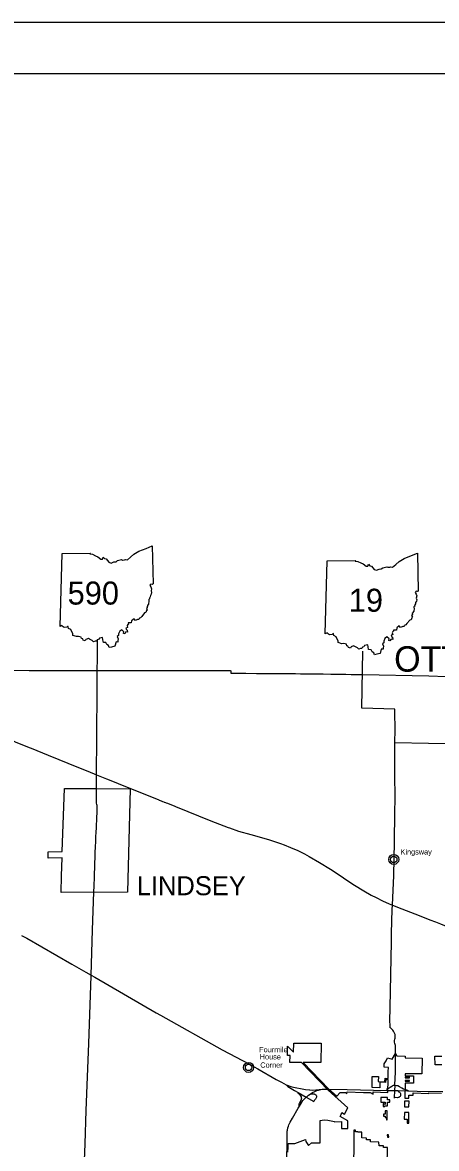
# Model space of a CAD drawing. Extents: x 0 to 798, y 0 to 440.
# Drawn here: x 286.7 to 368.1, y 218.5 to 440 of the extents above; entities that cross this region are included whole.
import ezdxf

# ---------------------------------------------------------------- set-up
doc = ezdxf.new("R2010")
doc.units = 0
for name, color, linetype in [('DV_X_Corp_Line', 7, 'Continuous'), ('GM_X_Adjacent_County_Text', 7, 'Continuous'), ('GM_X_Corporation_Text', 7, 'Continuous'), ('GM_X_County', 7, 'Continuous'), ('GM_X_Interchange_Ramps', 7, 'Continuous'), ('GM_X_Interstate_Route', 7, 'Continuous'), ('GM_X_State_Route', 7, 'Continuous'), ('GM_X_US_Route', 7, 'Continuous'), ('PV_P_Text', 7, 'Continuous'), ('SH_Border', 7, 'Continuous'), ('SH_Cut_Line', 7, 'Continuous')]:
    doc.layers.add(name, color=color, linetype=linetype)

msp = doc.modelspace()

# ---------------------------------------------------------------- linework, layer by layer
at = {"layer": 'DV_X_Corp_Line'}
for points in [[(294.48, 275.7), (291.76, 275.59), (291.77, 276.85), (294.52, 276.95), (294.94, 289.31), (301.23, 289.3), (307.86, 289.23), (307.38, 268.9), (294.27, 268.88), (294.36, 272.12)], [(361.98, 232.58), (361.98, 232.42), (362.83, 232.42), (362.83, 232.58)], [(361.97, 231.73), (362.82, 231.73), (362.82, 231.86), (361.98, 231.86)], [(357.18, 228.51), (357.18, 227.98), (357.22, 227.98), (357.22, 227.62), (358.06, 227.62), (358.06, 227.14), (357.68, 227.35), (357.68, 226.74), (357.97, 226.74), (357.97, 226.89), (358.5, 226.88), (358.5, 227.62), (359, 227.62), (359, 228.1), (358.53, 228.1), (358.54, 228.51)], [(361.86, 226.73), (362.72, 226.71), (362.74, 227.79), (361.87, 227.79)], [(358.02, 225.92), (358.02, 225.27), (357.73, 225.27), (357.73, 224.84), (358.02, 224.84), (358.02, 224.61), (358.34, 224.61), (358.34, 224.15), (358.47, 224.15), (358.46, 224.73), (358.45, 225.52), (358.46, 225.92)], [(361.82, 224.29), (362.35, 224.29), (362.35, 223.5), (362.72, 223.49), (362.72, 225.61), (361.85, 225.61)], [(358.47, 221.16), (358.49, 220.72), (358.74, 220.71), (358.72, 221.16)]]:
    msp.add_lwpolyline(points, close=True, dxfattribs=at)
for points in [[(338.88, 217.79), (338.97, 218.79), (338.97, 219.46), (340.29, 219.48), (340.81, 219.67), (342.38, 220.25), (342.42, 219.91), (342.99, 219.12), (343.56, 219.59), (345.24, 219.62), (345.24, 224), (346.07, 224.15), (346.77, 224.07), (348.07, 223.84), (348.04, 223.78), (349.45, 223.83), (349.45, 222.43), (350.72, 222.45), (350.72, 223.95), (349.21, 224.82), (349.38, 225.18), (349.51, 225.56), (350.06, 225.25), (350.7, 226.51), (346.86, 229.97), (341.6, 235.42), (339.32, 235.42), (339.34, 236.79), (338.84, 236.79), (338.85, 238.66), (340.03, 237.45), (340.06, 239.21), (345.45, 239.21), (345.38, 235.44), (341.9, 235.44), (346.99, 230.17), (348.54, 228.79), (349.19, 229.52), (350.23, 229.5), (350.54, 229.25), (350.56, 229.64), (353.8, 229.54), (355.08, 229.49), (355.71, 229.2), (355.72, 229.63), (358.56, 229.55), (358.62, 232.05), (358.15, 232.06), (358.14, 231.51), (357.02, 231.55), (356.99, 230.44), (355.46, 230.48), (355.52, 232.67), (356.71, 232.65), (356.69, 231.68), (358.01, 231.63), (358.03, 232.32), (358.63, 232.3), (358.66, 233.66), (358.71, 234.45), (357.87, 234.48), (357.88, 235.14), (358.23, 235.77), (358.53, 236.32), (359.42, 236.08), (360.07, 237.16), (360.33, 236.73), (361.98, 236.68), (362, 236.34), (365.32, 236.28), (365.26, 233.17), (361.99, 233.18), (361.98, 232.79), (363.64, 232.79), (363.63, 231.33), (361.97, 231.34), (361.91, 228.41), (362.69, 228.41), (362.69, 229), (363.55, 229.01), (363.59, 229.43), (366.61, 229.34), (366.63, 229.48), (369.16, 229.41)], [(369.23, 234.96), (367.86, 234.98), (367.85, 236.67), (369.22, 236.67)], [(358.45, 215.07), (358.48, 218.73), (357.71, 218.71), (357.71, 219.01), (356.84, 219), (356.83, 219.77), (355.18, 219.8), (355.18, 220.2), (354.36, 220.18), (354.36, 220.56), (353.45, 220.58), (353.47, 221.69), (352.64, 221.72), (352.64, 221.78), (352.21, 221.78), (352.21, 222.11), (351.91, 222.11), (351.89, 219.21), (351.83, 215.37)]]:
    msp.add_lwpolyline(points, dxfattribs=at)
for centre, radius in [((359.74, 275.36), 0.982), ((359.74, 275.36), 0.623), ((331.17, 234.45), 0.982), ((331.17, 234.45), 0.623)]:
    msp.add_circle(centre, radius, dxfattribs=at)
at = {"layer": 'GM_X_County'}
msp.add_lwpolyline([(281.3, 312.63), (287.98, 312.54), (301.39, 312.52), (301.93, 312.52), (302.64, 312.52), (303.69, 312.52), (304.8, 312.52), (305.75, 312.51), (307.02, 312.52), (307.92, 312.52), (308.45, 312.52), (309.05, 312.53), (310.14, 312.54), (310.71, 312.54), (311.7, 312.54), (312.27, 312.55), (314.12, 312.55), (314.59, 312.55), (314.66, 312.55), (314.98, 312.55), (315.76, 312.55), (316.87, 312.55), (317.32, 312.55), (318.39, 312.54), (320.24, 312.53), (320.85, 312.52), (321.76, 312.52), (322.24, 312.51), (322.74, 312.51), (323.44, 312.51), (324.34, 312.52), (327.09, 312.51), (327.58, 312.5), (327.69, 312.49), (327.71, 311.99), (330.61, 311.98), (332.73, 311.96), (333.63, 311.96), (340.32, 311.91), (340.36, 311.91), (340.43, 311.91), (341.36, 311.88), (342.43, 311.87), (344.19, 311.87), (345.88, 311.86), (347.36, 311.83), (348.69, 311.81), (349.44, 311.8), (350.31, 311.79), (351.37, 311.77), (352.15, 311.75), (353.17, 311.73), (353.57, 311.72), (366.64, 311.45), (370.09, 311.37)], dxfattribs=at)
at = {"layer": 'GM_X_Interchange_Ramps'}
for points in [[(360, 230.89), (359.91, 230.89), (359.77, 230.9), (359.65, 230.88), (359.51, 230.81), (359.36, 230.7), (359.01, 230.47), (358.85, 230.39), (358.7, 230.32), (358.54, 230.27), (358.42, 230.23), (358.37, 230.22), (358.37, 229.92)], [(340.9, 229.51), (340.85, 229.43), (341.1, 229.23), (341.28, 229.05), (341.41, 228.86), (341.51, 228.66), (341.55, 228.5), (341.57, 228.33), (341.54, 228.12), (341.47, 227.95), (341.15, 227.37), (341.07, 227.21), (341.06, 227.06), (341.07, 226.97), (341.13, 226.9), (341.2, 226.85)], [(343.46, 229.33), (343.51, 229.24), (343.71, 229.28), (343.91, 229.28), (344.09, 229.25), (344.24, 229.19), (344.39, 229.09), (344.47, 228.98), (344.53, 228.84), (344.55, 228.72), (344.53, 228.61), (344.5, 228.48), (344.44, 228.36), (344.32, 228.21), (344.1, 227.92), (344, 227.75)], [(360.58, 229.88), (360.58, 229.73), (360.72, 229.67), (360.84, 229.61), (360.93, 229.53), (361.02, 229.43), (361.07, 229.29), (361.09, 229.15), (361.08, 229), (361.04, 228.87), (360.97, 228.73), (360.86, 228.64), (360.72, 228.56), (360.59, 228.53), (360.39, 228.5), (360.01, 228.51), (359.91, 228.5)]]:
    msp.add_lwpolyline(points, dxfattribs=at)
at = {"layer": 'GM_X_Interstate_Route'}
for points in [[(261.24, 310.79), (261.46, 310.64), (262.37, 310.05), (262.7, 309.84), (264.07, 309.02), (265.46, 308.27), (268.51, 306.71), (271.58, 305.16), (273.93, 303.96), (274.66, 303.59), (275.47, 303.19), (277.47, 302.18), (280.88, 300.44), (281.95, 299.92), (282.55, 299.64), (284.37, 298.87), (285.22, 298.52), (287.99, 297.39), (288.4, 297.24), (291.71, 295.9), (297.7, 293.48), (299.54, 292.73), (301.25, 292.04)], [(301.25, 292.04), (303.21, 291.25), (304.43, 290.75), (305.53, 290.32), (313.49, 287.1), (313.61, 287.04), (313.98, 286.9), (314.1, 286.85), (314.26, 286.79), (314.47, 286.71), (314.59, 286.65), (314.83, 286.56), (314.96, 286.5), (315.2, 286.41), (316.67, 285.82), (316.79, 285.76), (323.72, 282.94), (327.13, 281.64), (327.4, 281.55), (329.22, 280.95), (331.64, 280.28), (333.26, 279.82), (335.32, 279.22), (336.07, 278.99), (337.44, 278.51), (338.19, 278.23), (339.41, 277.74), (340.86, 277.1), (342.16, 276.46), (343.1, 275.97), (345.16, 274.79), (347.27, 273.44), (348.77, 272.44), (350.91, 271.03), (352.01, 270.3), (353.83, 269.19), (355.29, 268.35), (356.25, 267.85), (357.53, 267.21), (358.86, 266.63), (359.49, 266.36)], [(359.49, 266.36), (361.31, 265.65), (364.76, 264.31), (366.84, 263.5), (367.95, 263.07), (368.92, 262.7), (370.05, 262.27), (371.03, 261.89), (372.38, 261.37), (373.07, 261.1), (374.22, 260.65), (374.53, 260.53)]]:
    msp.add_lwpolyline(points, dxfattribs=at)
at = {"layer": 'GM_X_State_Route'}
for points in [[(301.25, 292.04), (301.31, 299.32), (301.43, 318.53)], [(359.99, 300.38), (359.97, 304.89), (359.97, 304.91), (353.48, 305.11), (353.63, 316.36)], [(359.98, 298.93), (359.98, 298.93), (359.99, 300.29), (359.99, 300.38)], [(359.98, 296.57), (359.97, 298.39), (359.98, 298.93)], [(359.97, 298.39), (366.57, 298.25), (369.86, 298.14), (384.26, 297.72)], [(359.98, 292.78), (359.98, 296.55), (359.98, 296.57)], [(359.73, 272.22), (359.86, 278.83), (359.88, 279.68), (359.95, 283.71), (359.96, 284.77), (359.95, 285.12), (360, 286.83), (359.98, 292.75), (359.98, 292.78)], [(301.23, 289.3), (301.25, 292.04)], [(301.16, 280.4), (301.36, 284.84), (301.39, 285.96), (301.38, 286), (301.34, 286.2), (301.24, 286.46), (301.23, 286.75), (301.23, 289.3)], [(301.05, 277.88), (301.05, 277.92), (301.09, 278.83), (301.13, 279.64), (301.14, 279.88)], [(301.14, 279.88), (301.15, 280.17), (301.16, 280.4)], [(300.99, 276.45), (301, 276.61), (301, 276.69), (301.01, 276.81), (301.05, 277.77), (301.05, 277.88)], [(300.92, 274.2), (300.93, 274.47), (300.95, 275.14), (300.96, 275.28), (300.99, 276.29), (300.99, 276.45)], [(300.75, 269.22), (300.78, 269.94), (300.86, 272.12), (300.92, 274.17), (300.92, 274.2)], [(359.32, 260.85), (359.45, 265.54), (359.49, 266.36), (359.73, 272.22)], [(300.21, 252.59), (300.47, 261.42), (300.75, 269.01), (300.75, 269.22)], [(359.06, 246.22), (359.27, 259.15), (359.32, 260.85)], [(298.6, 208.69), (298.59, 208.92), (298.76, 212.81), (298.99, 219.43), (299.23, 225.95), (299.47, 232.59), (299.71, 239.18), (300.21, 252.46), (300.21, 252.59)], [(359.05, 245.82), (359.06, 246.22), (359.06, 246.22)], [(360.06, 238.44), (360.06, 238.74), (359.93, 239.17), (359.88, 239.45), (359.88, 239.58), (359.9, 239.73), (359.96, 240), (359.99, 240.19), (360.02, 240.41), (360.03, 240.6), (360.01, 240.91), (359.9, 241.21), (359.72, 241.56), (359.56, 241.79), (359.29, 242.04), (359.07, 242.21), (359.02, 242.27), (359.01, 242.37), (358.99, 243.94), (359.05, 245.82)], [(360.06, 238.15), (360.06, 238.44), (360.06, 238.44)], [(360.07, 237.55), (360.06, 238.15)], [(360.07, 237.16), (360.07, 237.55), (360.07, 237.55)], [(360.1, 233.5), (360.11, 233.67), (360.07, 237.16)], [(360.28, 230.86), (360.27, 230.86), (360, 230.89), (359.98, 231.03), (360.1, 233.5)], [(359.9, 228.42), (359.91, 228.5), (359.96, 229.89), (360, 230.89)], [(362.5, 229.88), (362.5, 229.88), (362.12, 230.02), (361.65, 230.18), (361.32, 230.38), (360.86, 230.66), (360.52, 230.82), (360.28, 230.86), (360.28, 230.86)], [(362.64, 229.83), (362.5, 229.88)]]:
    msp.add_lwpolyline(points, dxfattribs=at)
at = {"layer": 'GM_X_US_Route'}
for points in [[(286.5, 260.43), (287.53, 259.85)], [(287.53, 259.85), (296.42, 254.76)], [(296.42, 254.76), (299.18, 253.18)], [(299.18, 253.18), (300.21, 252.59)], [(300.21, 252.59), (300.21, 252.59), (300.9, 252.19)], [(300.9, 252.19), (312.99, 245.17), (313.85, 244.7), (326, 237.94), (331.35, 235.07)], [(331.35, 235.07), (332.28, 234.57), (332.97, 234.18)], [(332.97, 234.18), (336.61, 232.1), (336.61, 232.1)], [(336.61, 232.1), (337.64, 231.52), (338.55, 231.04), (339.69, 230.64), (342.4, 230.13), (343.19, 230.02), (343.22, 230.02)], [(338.55, 231.04), (338.68, 230.92), (338.91, 230.71), (339.22, 230.5), (340.21, 229.9), (340.9, 229.51), (342.51, 228.6), (344, 227.75)], [(341.2, 226.85), (341.88, 227.94), (342.23, 228.35), (342.24, 228.35)], [(342.24, 228.35), (342.25, 228.37), (342.51, 228.6), (342.59, 228.68), (342.67, 228.76), (342.97, 229.01), (343.46, 229.33), (343.78, 229.53), (344.21, 229.74), (344.76, 229.95), (344.9, 229.99)], [(343.22, 230.02), (343.8, 230), (345.67, 230.2)], [(344.9, 229.99), (344.92, 230), (345.14, 230.06), (345.67, 230.2)], [(345.67, 230.2), (345.67, 230.2), (346.62, 230.18)], [(346.62, 230.18), (346.89, 230.17)], [(346.89, 230.17), (350.55, 230.09), (358.37, 229.92), (358.72, 229.92)], [(358.72, 229.92), (359.96, 229.89), (360.43, 229.88)], [(360.43, 229.88), (360.58, 229.88), (362.44, 229.84)], [(362.44, 229.84), (362.64, 229.83), (364.33, 229.81), (364.36, 229.81)], [(364.36, 229.81), (369.27, 229.74), (369.38, 229.73)], [(338.69, 215.45), (338.78, 220.46), (338.8, 221.88), (338.81, 222.12), (338.91, 222.56), (339.02, 222.9), (339.12, 223.18), (339.36, 223.69), (339.81, 224.46), (340.92, 226.41), (341.2, 226.85)]]:
    msp.add_lwpolyline(points, dxfattribs=at)
at = {"layer": 'PV_P_Text'}
for p, q in [((294.07, 321.16), (294.47, 335.53)), ((294.07, 321.16), (294.47, 335.53)), ((346.27, 319.75), (346.67, 334.11)), ((346.27, 319.75), (346.67, 334.11))]:
    msp.add_line(p, q, dxfattribs=at)
for points in [[(294.47, 335.53), (300.04, 335.62), (299.95, 335.45), (300.48, 335.41), (301.04, 335.1), (301.51, 334.91), (302.09, 334.45), (302.43, 334.46), (302.58, 334.83), (302.85, 334.54), (303.16, 334.49), (303.7, 333.81), (304.15, 333.66), (304.69, 333.89), (305.09, 333.93), (305.38, 334.16), (306.15, 334.36), (306.36, 334.24), (306.77, 334.27), (306.97, 334.36), (307.32, 334.28), (307.94, 334.8), (308.58, 335.41), (309.57, 336), (311.04, 336.55), (312.2, 337.04), (312.37, 329.59)], [(294.47, 335.53), (300.04, 335.62), (299.95, 335.45), (300.48, 335.41), (301.04, 335.1), (301.51, 334.91), (302.09, 334.45), (302.43, 334.46), (302.58, 334.83), (302.85, 334.54), (303.16, 334.49), (303.7, 333.81), (304.15, 333.66), (304.69, 333.89), (305.09, 333.93), (305.38, 334.16), (306.15, 334.36), (306.36, 334.24), (306.77, 334.27), (306.97, 334.36), (307.32, 334.28), (307.94, 334.8), (308.58, 335.41), (309.57, 336), (311.04, 336.55), (312.2, 337.04), (312.37, 329.59)], [(346.67, 334.11), (352.24, 334.2), (352.15, 334.03), (352.68, 333.99), (353.24, 333.69), (353.71, 333.49), (354.29, 333.04), (354.63, 333.04), (354.78, 333.42), (355.04, 333.13), (355.36, 333.08), (355.9, 332.39), (356.35, 332.24), (356.89, 332.48), (357.29, 332.51), (357.58, 332.75), (358.35, 332.95), (358.56, 332.83), (358.96, 332.85), (359.17, 332.94), (359.52, 332.86), (360.14, 333.38), (360.78, 334), (361.77, 334.58), (363.24, 335.13), (364.4, 335.62), (364.57, 328.17)], [(346.67, 334.11), (352.24, 334.2), (352.15, 334.03), (352.68, 333.99), (353.24, 333.69), (353.71, 333.49), (354.29, 333.04), (354.63, 333.04), (354.78, 333.42), (355.04, 333.13), (355.36, 333.08), (355.9, 332.39), (356.35, 332.24), (356.89, 332.48), (357.29, 332.51), (357.58, 332.75), (358.35, 332.95), (358.56, 332.83), (358.96, 332.85), (359.17, 332.94), (359.52, 332.86), (360.14, 333.38), (360.78, 334), (361.77, 334.58), (363.24, 335.13), (364.4, 335.62), (364.57, 328.17)], [(312.37, 329.59), (312.2, 329.48), (311.93, 329.53), (311.75, 329.32), (311.97, 328.97), (312.08, 328.6), (311.98, 328.2), (312.08, 327.86), (312.01, 327.58), (311.85, 327.3), (311.79, 327.04), (311.65, 326.76), (311.66, 326.6), (311.52, 326.48), (311.55, 326.01), (311.48, 325.75), (311.5, 325.53), (311.28, 325.47), (311.33, 325.29), (311.19, 325.14), (311.22, 324.9), (311.06, 324.74), (311.22, 324.43), (311.09, 324.33), (310.99, 323.95), (310.71, 323.87), (310.14, 323.18), (309.94, 322.91), (309.71, 322.85), (309.59, 322.58), (309.31, 322.58), (308.9, 322.39), (308.63, 322.71), (308.15, 322.33), (308.1, 321.88), (307.5, 321.89), (307.52, 321.67), (307.39, 321.6), (307.26, 321.37), (307.34, 320.97), (307.05, 320.87), (307.09, 320.63), (307.27, 320.49), (307.35, 320.04), (307.05, 320.13), (306.81, 319.76), (306.55, 319.84), (306.64, 320.16), (306.21, 320.55), (305.81, 320.24), (305.6, 319.75), (305.6, 319.42), (305.3, 319.22), (305.49, 318.75), (305.46, 318.43), (305.46, 318.12), (305.09, 318.14), (304.86, 317.31)], [(312.37, 329.59), (312.2, 329.48), (311.93, 329.53), (311.75, 329.32), (311.97, 328.97), (312.08, 328.6), (311.98, 328.2), (312.08, 327.86), (312.01, 327.58), (311.85, 327.3), (311.79, 327.04), (311.65, 326.76), (311.66, 326.6), (311.52, 326.48), (311.55, 326.01), (311.48, 325.75), (311.5, 325.53), (311.28, 325.47), (311.33, 325.29), (311.19, 325.14), (311.22, 324.9), (311.06, 324.74), (311.22, 324.43), (311.09, 324.33), (310.99, 323.95), (310.71, 323.87), (310.14, 323.18), (309.94, 322.91), (309.71, 322.85), (309.59, 322.58), (309.31, 322.58), (308.9, 322.39), (308.63, 322.71), (308.15, 322.33), (308.1, 321.88), (307.5, 321.89), (307.52, 321.67), (307.39, 321.6), (307.26, 321.37), (307.34, 320.97), (307.05, 320.87), (307.09, 320.63), (307.27, 320.49), (307.35, 320.04), (307.05, 320.13), (306.81, 319.76), (306.55, 319.84), (306.64, 320.16), (306.21, 320.55), (305.81, 320.24), (305.6, 319.75), (305.6, 319.42), (305.3, 319.22), (305.49, 318.75), (305.46, 318.43), (305.46, 318.12), (305.09, 318.14), (304.86, 317.31)], [(364.57, 328.17), (364.4, 328.06), (364.13, 328.11), (363.95, 327.9), (364.17, 327.56), (364.28, 327.19), (364.18, 326.78), (364.28, 326.45), (364.21, 326.17), (364.05, 325.89), (363.99, 325.62), (363.84, 325.34), (363.86, 325.18), (363.72, 325.06), (363.75, 324.59), (363.68, 324.33), (363.7, 324.11), (363.48, 324.05), (363.53, 323.87), (363.39, 323.73), (363.42, 323.48), (363.26, 323.33), (363.41, 323.01), (363.29, 322.91), (363.19, 322.53), (362.9, 322.46), (362.34, 321.76), (362.14, 321.5), (361.91, 321.43), (361.79, 321.16), (361.51, 321.16), (361.09, 320.97), (360.82, 321.3), (360.35, 320.91), (360.3, 320.46), (359.7, 320.48), (359.72, 320.25), (359.59, 320.18), (359.46, 319.96), (359.53, 319.55), (359.25, 319.45), (359.29, 319.22), (359.47, 319.07), (359.55, 318.63), (359.25, 318.72), (359, 318.34), (358.75, 318.43), (358.84, 318.75), (358.41, 319.13), (358.01, 318.82), (357.8, 318.33), (357.8, 318), (357.5, 317.8), (357.69, 317.33), (357.66, 317.01), (357.66, 316.71), (357.29, 316.72), (357.06, 315.89)], [(364.57, 328.17), (364.4, 328.06), (364.13, 328.11), (363.95, 327.9), (364.17, 327.56), (364.28, 327.19), (364.18, 326.78), (364.28, 326.45), (364.21, 326.17), (364.05, 325.89), (363.99, 325.62), (363.84, 325.34), (363.86, 325.18), (363.72, 325.06), (363.75, 324.59), (363.68, 324.33), (363.7, 324.11), (363.48, 324.05), (363.53, 323.87), (363.39, 323.73), (363.42, 323.48), (363.26, 323.33), (363.41, 323.01), (363.29, 322.91), (363.19, 322.53), (362.9, 322.46), (362.34, 321.76), (362.14, 321.5), (361.91, 321.43), (361.79, 321.16), (361.51, 321.16), (361.09, 320.97), (360.82, 321.3), (360.35, 320.91), (360.3, 320.46), (359.7, 320.48), (359.72, 320.25), (359.59, 320.18), (359.46, 319.96), (359.53, 319.55), (359.25, 319.45), (359.29, 319.22), (359.47, 319.07), (359.55, 318.63), (359.25, 318.72), (359, 318.34), (358.75, 318.43), (358.84, 318.75), (358.41, 319.13), (358.01, 318.82), (357.8, 318.33), (357.8, 318), (357.5, 317.8), (357.69, 317.33), (357.66, 317.01), (357.66, 316.71), (357.29, 316.72), (357.06, 315.89)], [(304.86, 317.31), (304.21, 317.15), (303.76, 317.06), (303.6, 317.43), (303.28, 317.63), (303.07, 318.01), (302.6, 318.06), (302.49, 318.58), (302.44, 319), (301.81, 318.89), (301.63, 318.64), (301.41, 318.57), (301.28, 318.31), (300.97, 318.29), (300.64, 318.16), (300.43, 318.42), (299.89, 318.67), (299.65, 318.81), (299.14, 318.6), (299.03, 318.36), (298.63, 318.47), (298.54, 318.74), (298.29, 318.82), (298.24, 319.1), (297.72, 319.25), (297.32, 319.19), (296.61, 319.42), (296.57, 319.8), (296.33, 320.26), (296.21, 320.58), (295.76, 320.82), (295.67, 321.2), (295.53, 321.19), (295.4, 321.03), (294.91, 320.96), (294.71, 321.12), (294.43, 321.38), (294.07, 321.16)], [(304.86, 317.31), (304.21, 317.15), (303.76, 317.06), (303.6, 317.43), (303.28, 317.63), (303.07, 318.01), (302.6, 318.06), (302.49, 318.58), (302.44, 319), (301.81, 318.89), (301.63, 318.64), (301.41, 318.57), (301.28, 318.31), (300.97, 318.29), (300.64, 318.16), (300.43, 318.42), (299.89, 318.67), (299.65, 318.81), (299.14, 318.6), (299.03, 318.36), (298.63, 318.47), (298.54, 318.74), (298.29, 318.82), (298.24, 319.1), (297.72, 319.25), (297.32, 319.19), (296.61, 319.42), (296.57, 319.8), (296.33, 320.26), (296.21, 320.58), (295.76, 320.82), (295.67, 321.2), (295.53, 321.19), (295.4, 321.03), (294.91, 320.96), (294.71, 321.12), (294.43, 321.38), (294.07, 321.16)], [(357.06, 315.89), (356.41, 315.74), (355.96, 315.64), (355.8, 316.02), (355.48, 316.21), (355.27, 316.59), (354.8, 316.64), (354.69, 317.16), (354.64, 317.58), (354.01, 317.48), (353.83, 317.22), (353.61, 317.15), (353.48, 316.89), (353.17, 316.87), (352.84, 316.75), (352.63, 317), (352.09, 317.26), (351.85, 317.39), (351.34, 317.18), (351.23, 316.94), (350.83, 317.05), (350.73, 317.32), (350.49, 317.4), (350.44, 317.69), (349.92, 317.84), (349.52, 317.78), (348.81, 318.01), (348.77, 318.38), (348.53, 318.84), (348.41, 319.16), (347.96, 319.4), (347.87, 319.78), (347.73, 319.77), (347.6, 319.62), (347.1, 319.55), (346.91, 319.7), (346.63, 319.97), (346.27, 319.75)], [(357.06, 315.89), (356.41, 315.74), (355.96, 315.64), (355.8, 316.02), (355.48, 316.21), (355.27, 316.59), (354.8, 316.64), (354.69, 317.16), (354.64, 317.58), (354.01, 317.48), (353.83, 317.22), (353.61, 317.15), (353.48, 316.89), (353.17, 316.87), (352.84, 316.75), (352.63, 317), (352.09, 317.26), (351.85, 317.39), (351.34, 317.18), (351.23, 316.94), (350.83, 317.05), (350.73, 317.32), (350.49, 317.4), (350.44, 317.69), (349.92, 317.84), (349.52, 317.78), (348.81, 318.01), (348.77, 318.38), (348.53, 318.84), (348.41, 319.16), (347.96, 319.4), (347.87, 319.78), (347.73, 319.77), (347.6, 319.62), (347.1, 319.55), (346.91, 319.7), (346.63, 319.97), (346.27, 319.75)]]:
    msp.add_lwpolyline(points, dxfattribs=at)
at = {"layer": 'SH_Border'}
msp.add_lwpolyline([(30, 430), (670, 430), (670, 10), (30, 10)], close=True, dxfattribs=at)
at = {"layer": 'SH_Cut_Line'}
msp.add_lwpolyline([(0, 0), (680, 0), (680, 440), (0, 440)], close=True, dxfattribs=at)

# ---------------------------------------------------------------- texts
at = {"layer": 'DV_X_Corp_Line'}
for s, p in [('Kingsway', (361.07, 276.33)), ('Fourmile', (333.26, 237.43)), ('House', (333.37, 236.02)), ('Corner', (333.48, 234.4))]:
    msp.add_text(s, height=1.042, rotation=0, dxfattribs=at).set_placement(p)
at = {"layer": 'GM_X_Adjacent_County_Text'}
msp.add_text('OTTAWA COUNTY', height=5, rotation=0.071, dxfattribs=at).set_placement((359.82, 312.3))
at = {"layer": 'GM_X_Corporation_Text'}
msp.add_text('LINDSEY', height=3.75, rotation=0, dxfattribs=at).set_placement((309.17, 268.32))
at = {"layer": 'PV_P_Text'}
for s, p in [('590', (295.57, 325.5)), ('19', (350.89, 324.09))]:
    msp.add_text(s, height=4.528, dxfattribs=at).set_placement(p)

doc.saveas('drawing.dxf')
